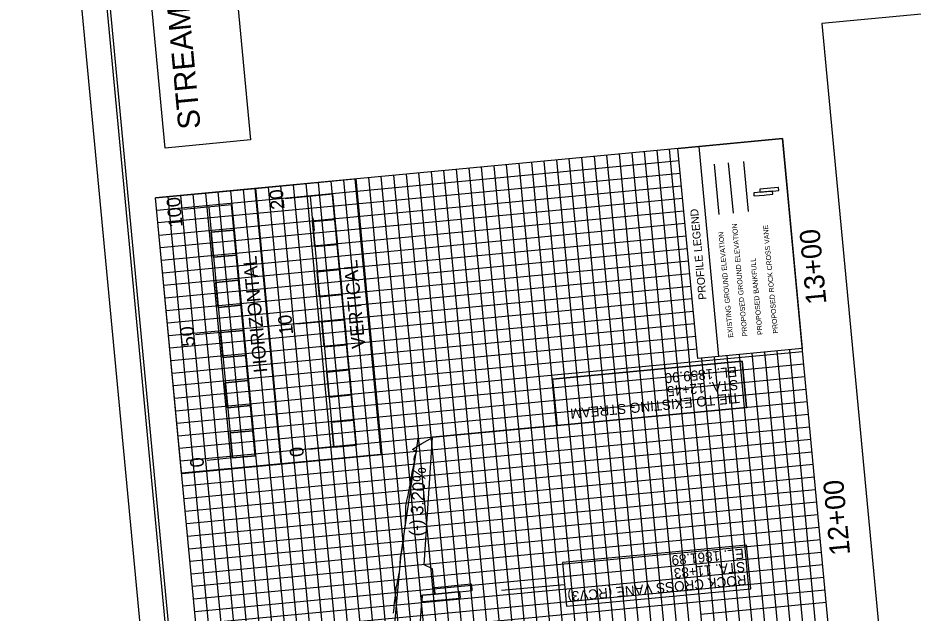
# Model space of a CAD drawing. Extents: x 554635 to 555260, y 497951 to 498841.
# Drawn here: x 554635.2 to 554990.7, y 498281.2 to 498517.4 of the extents above; entities that cross this region are included whole.
import ezdxf

# ---------------------------------------------------------------- set-up
doc = ezdxf.new("R2010")
doc.units = 0
for name, color, linetype in [('Default', 7, 'Continuous'), ('Exist Vertical Profile Ground Line', 7, 'Continuous'), ('Exist Vertical Profile Horizontal Axis Label Major', 7, 'Continuous'), ('Prop Drainage Ditch Boundaries', 7, 'Continuous'), ('Prop Erosion Rip Rap Single Stone CELL', 7, 'Continuous'), ('Prop NEU Vane Rock Cross With Step Pools Detail CELL', 7, 'Continuous'), ('Prop Plan Preparation Fill In Wetlands Legend CELL', 7, 'Continuous'), ('Prop Plan Preparation Sheet Bridge Report Non FEMA CELL', 7, 'Continuous'), ('Prop Vertical Profile Ditch Grade Median', 7, 'Continuous'), ('Prop Vertical Profile Ditch Grade Median Label', 7, 'Continuous'), ('Prop VPI Ditch Grade Median Label', 7, 'Continuous'), ('Prop VPT Ditch Grade Median Label', 7, 'Continuous'), ('Sheet Cross Section Scale CELL', 7, 'Continuous'), ('Sheet Layout Plan Border', 7, 'Continuous'), ('Sheet Plan CELL', 7, 'Continuous'), ('Sheet Plot Border Inside CELL', 7, 'Continuous'), ('Sheet Plot Border Outside CELL', 7, 'Continuous')]:
    doc.layers.add(name, color=color, linetype=linetype)

msp = doc.modelspace()

# ---------------------------------------------------------------- linework, layer by layer
at = {"layer": 'Default'}
msp.add_line((554752.4, 498438.09), (554752.87, 498433.11), dxfattribs=at)
at = {"layer": 'Exist Vertical Profile Ground Line'}
msp.add_line((554913.68, 498439.42), (554911.8, 498459.39), dxfattribs=at)
for points in [[(554787.44, 498304.57), (554787.66, 498305.6), (554787.88, 498306.62), (554788.11, 498307.65), (554788.26, 498308.67), (554788.35, 498309.68), (554788.45, 498310.69), (554788.54, 498311.71), (554788.63, 498312.72), (554788.73, 498313.74), (554788.83, 498314.75), (554788.98, 498315.77), (554789.12, 498316.79), (554789.16, 498317.79), (554789.18, 498318.8), (554789.21, 498319.81), (554789.23, 498320.81), (554789.26, 498321.82), (554789.29, 498322.83), (554789.33, 498323.84), (554789.53, 498324.86), (554789.73, 498325.88), (554789.94, 498326.91), (554790.14, 498327.93), (554790.34, 498328.95), (554790.55, 498329.98), (554790.75, 498331), (554790.94, 498332.02), (554791.12, 498333.05), (554791.3, 498334.07), (554791.48, 498335.09), (554791.67, 498336.11), (554791.85, 498337.13), (554792.03, 498338.15), (554792.26, 498339.18), (554792.51, 498340.21), (554792.67, 498341.23), (554792.63, 498342.23), (554792.73, 498343.24), (554793.16, 498344.29), (554793.6, 498345.33), (554791.9, 498346.18), (554793.62, 498347.34), (554795.68, 498348.54), (554797.75, 498349.74), (554799.81, 498350.94), (554799.85, 498350.97)], [(554784.44, 498281.19), (554784.53, 498282.2), (554784.62, 498283.21), (554784.7, 498284.23), (554784.79, 498285.24), (554784.87, 498286.25), (554784.99, 498287.27), (554785.12, 498288.28), (554785.24, 498289.3), (554785.37, 498290.32), (554785.5, 498291.33), (554785.67, 498292.35), (554785.9, 498293.38), (554786.12, 498294.4), (554786.31, 498295.43), (554786.51, 498296.45), (554786.7, 498297.47), (554786.84, 498298.49), (554786.91, 498299.5), (554786.97, 498300.51), (554787.04, 498301.52), (554787.11, 498302.53), (554787.21, 498303.55), (554787.44, 498304.57)]]:
    msp.add_lwpolyline(points, dxfattribs=at)
at = {"layer": 'Prop Drainage Ditch Boundaries'}
msp.add_line((554925.35, 498440.52), (554923.47, 498460.4), dxfattribs=at)
msp.add_lwpolyline([(554756.46, 498100.75), (554778.24, 498153.03), (554776.77, 498203.12), (554782.76, 498253.91), (554787.47, 498304.58), (554794.13, 498350.41)], dxfattribs=at)
at = {"layer": 'Prop Erosion Rip Rap Single Stone CELL'}
for p, q in [((554927.42, 498447.81), (554927.5, 498446.9)), ((554934.76, 498448.67), (554927.51, 498447.98)), ((554929.79, 498449.29), (554929.87, 498448.37)), ((554937.13, 498450.15), (554929.88, 498449.46)), ((554934.76, 498448.67), (554936.15, 498448.8)), ((554934.97, 498447.6), (554934.88, 498448.51)), ((554936.15, 498448.8), (554937.25, 498448.9)), ((554937.34, 498449.08), (554937.25, 498449.99)), ((554932.39, 498447.19), (554933.78, 498447.32)), ((554933.78, 498447.32), (554934.88, 498447.43)), ((554815.25, 498292.64), (554800.74, 498291.27)), ((554815.67, 498290.5), (554815.49, 498292.33)), ((554795.77, 498288), (554795.65, 498286.15)), ((554800.98, 498288.78), (554796.07, 498288.31)), ((554800.56, 498290.91), (554800.73, 498289.09)), ((554808.74, 498289.51), (554800.98, 498288.78)), ((554810.51, 498289.68), (554808.74, 498289.51)), ((554810.51, 498289.68), (554813.29, 498289.94)), ((554810.92, 498287.54), (554810.75, 498289.37)), ((554813.29, 498289.94), (554815.48, 498290.15)), ((554796.01, 498285.8), (554810.74, 498287.19))]:
    msp.add_line(p, q, dxfattribs=at)
for points in [[(554929.99, 498448.22), (554933.88, 498448.59), (554934.76, 498448.67)], [(554927.62, 498446.74), (554931.51, 498447.11), (554932.39, 498447.19)], [(554800.98, 498288.78), (554808.74, 498289.51), (554810.51, 498289.68)]]:
    msp.add_lwpolyline(points, dxfattribs=at)
for centre, start, end in [((554796.1, 498287.98), 95.4008, 176.3197), ((554795.98, 498286.13), 176.3197, 275.4008)]:
    msp.add_arc(centre, 0.333, start, end, dxfattribs=at)
for centre, major_axis, start_param, end_param in [((554927.52, 498447.82), (0.016, -0.166), 3.141593, 4.712389), ((554929.89, 498449.3), (0.016, -0.166), 3.141593, 4.712389), ((554929.98, 498448.38), (0.016, -0.166), 4.712389, 6.283185), ((554934.78, 498448.5), (-0.016, 0.166), 4.712389, 6.283185), ((554937.15, 498449.98), (-0.016, 0.166), 4.712389, 6.283185), ((554937.23, 498449.07), (0.016, -0.166), 0, 1.570796), ((554927.61, 498446.91), (0.016, -0.166), 4.712389, 6.283185), ((554934.86, 498447.59), (0.016, -0.166), 0, 1.570796), ((554800.77, 498290.93), (0.031, -0.332), 3.141593, 4.712389), ((554815.28, 498292.31), (-0.031, 0.332), 4.712389, 6.283185), ((554800.94, 498289.11), (0.031, -0.332), 4.712389, 6.283185), ((554810.54, 498289.35), (-0.031, 0.332), 5.974663, 6.283185), ((554810.54, 498289.35), (-0.031, 0.332), 4.712389, 5.974663), ((554815.45, 498290.48), (0.031, -0.332), 0, 1.570796), ((554810.71, 498287.52), (0.031, -0.332), 0, 1.570796)]:
    msp.add_ellipse(centre, major_axis=major_axis, ratio=0.64, start_param=start_param, end_param=end_param, dxfattribs=at)
at = {"layer": 'Prop NEU Vane Rock Cross With Step Pools Detail CELL'}
msp.add_lwpolyline([(554693.71, 498465.77), (554674.74, 498666.49), (554708.62, 498669.7), (554727.59, 498468.97)], close=True, dxfattribs=at)
at = {"layer": 'Prop Plan Preparation Fill In Wetlands Legend CELL'}
msp.add_line((554905.61, 498466.41), (554913.49, 498383.06), dxfattribs=at)
msp.add_lwpolyline([(554905.19, 498382.28), (554897.31, 498465.63), (554938.81, 498469.55), (554946.69, 498386.2)], close=True, dxfattribs=at)
at = {"layer": 'Prop Plan Preparation Sheet Bridge Report Non FEMA CELL'}
for p, q in [((554938.81, 498469.55), (554889.03, 498464.85)), ((554975.22, 498084.39), (554938.81, 498469.55)), ((554889.03, 498464.85), (554689.92, 498446.02)), ((554892.11, 498113.58), (554859.16, 498462.02)), ((554897.09, 498114.05), (554864.14, 498462.49)), ((554902.06, 498114.52), (554869.12, 498462.96)), ((554907.04, 498114.99), (554874.1, 498463.43)), ((554912.02, 498115.46), (554879.08, 498463.9)), ((554917, 498115.93), (554884.05, 498464.38)), ((554925.45, 498079.69), (554889.03, 498464.85)), ((554925.45, 498079.69), (554889.03, 498464.85)), ((554926.95, 498116.87), (554894.01, 498465.32)), ((554889.5, 498459.87), (554690.39, 498441.04)), ((554857.26, 498110.28), (554824.32, 498458.73)), ((554862.24, 498110.75), (554829.3, 498459.2)), ((554867.22, 498111.22), (554834.28, 498459.67)), ((554875.67, 498074.98), (554839.25, 498460.14)), ((554877.17, 498112.16), (554844.23, 498460.61)), ((554882.15, 498112.64), (554849.21, 498461.08)), ((554887.13, 498113.11), (554854.19, 498461.55)), ((554897.78, 498460.65), (554889.5, 498459.87)), ((554889.97, 498454.89), (554690.86, 498436.07)), ((554817.44, 498106.52), (554784.5, 498454.96)), ((554825.89, 498070.27), (554789.48, 498455.43)), ((554827.4, 498107.46), (554794.45, 498455.9)), ((554832.37, 498107.93), (554799.43, 498456.38)), ((554837.35, 498108.4), (554804.41, 498456.85)), ((554842.33, 498108.87), (554809.39, 498457.32)), ((554847.31, 498109.34), (554814.36, 498457.79)), ((554852.29, 498109.81), (554819.34, 498458.26)), ((554898.25, 498455.67), (554889.97, 498454.89)), ((554777.62, 498102.75), (554744.68, 498451.2)), ((554782.6, 498103.22), (554749.65, 498451.67)), ((554787.57, 498103.69), (554754.63, 498452.14)), ((554792.55, 498104.16), (554759.61, 498452.61)), ((554797.53, 498104.63), (554764.59, 498453.08)), ((554802.51, 498105.11), (554769.56, 498453.55)), ((554807.48, 498105.58), (554774.54, 498454.02)), ((554812.46, 498106.05), (554779.52, 498454.49)), ((554890.44, 498449.91), (554691.33, 498431.09)), ((554742.77, 498099.46), (554709.83, 498447.9)), ((554747.75, 498099.93), (554714.81, 498448.37)), ((554752.73, 498100.4), (554719.79, 498448.85)), ((554757.71, 498100.87), (554724.76, 498449.32)), ((554762.68, 498101.34), (554729.74, 498449.79)), ((554767.66, 498101.81), (554734.72, 498450.26)), ((554776.11, 498065.57), (554739.7, 498450.73)), ((554898.72, 498450.7), (554890.44, 498449.91)), ((554726.33, 498060.86), (554689.92, 498446.02)), ((554890.91, 498444.94), (554691.8, 498426.11)), ((554727.84, 498098.05), (554694.9, 498446.49)), ((554732.82, 498098.52), (554699.87, 498446.96)), ((554737.8, 498098.99), (554704.85, 498447.43)), ((554899.19, 498445.72), (554890.91, 498444.94)), ((554899.66, 498440.74), (554891.38, 498439.96)), ((554891.38, 498439.96), (554692.27, 498421.13)), ((554891.86, 498434.98), (554692.74, 498416.15)), ((554900.13, 498435.76), (554891.86, 498434.98)), ((554892.33, 498430), (554693.21, 498411.18)), ((554900.6, 498430.78), (554892.33, 498430)), ((554892.8, 498425.02), (554693.68, 498406.2)), ((554901.07, 498425.81), (554892.8, 498425.02)), ((554893.27, 498420.05), (554694.15, 498401.22)), ((554901.54, 498420.83), (554893.27, 498420.05)), ((554902.01, 498415.85), (554893.74, 498415.07)), ((554893.74, 498415.07), (554694.63, 498396.24)), ((554894.21, 498410.09), (554695.1, 498391.27)), ((554902.48, 498410.87), (554894.21, 498410.09)), ((554894.68, 498405.11), (554695.57, 498386.29)), ((554902.95, 498405.89), (554894.68, 498405.11)), ((554895.15, 498400.13), (554696.04, 498381.31)), ((554903.43, 498400.92), (554895.15, 498400.13)), ((554895.62, 498395.16), (554696.51, 498376.33)), ((554903.9, 498395.94), (554895.62, 498395.16)), ((554904.37, 498390.96), (554896.09, 498390.18)), ((554896.09, 498390.18), (554696.98, 498371.35)), ((554896.56, 498385.2), (554697.45, 498366.38)), ((554904.84, 498385.98), (554896.56, 498385.2)), ((554946.81, 498384.93), (554897.03, 498380.22)), ((554946.86, 498118.75), (554921.8, 498383.85)), ((554951.84, 498119.22), (554926.78, 498384.32)), ((554956.82, 498119.69), (554931.76, 498384.79)), ((554961.8, 498120.16), (554936.73, 498385.26)), ((554966.77, 498120.64), (554941.71, 498385.73)), ((554897.03, 498380.22), (554697.92, 498361.4)), ((554931.93, 498117.34), (554906.87, 498382.44)), ((554936.91, 498117.81), (554911.84, 498382.91)), ((554941.89, 498118.28), (554916.82, 498383.38)), ((554947.28, 498379.95), (554897.5, 498375.25)), ((554897.5, 498375.25), (554698.39, 498356.42)), ((554947.75, 498374.97), (554897.97, 498370.27)), ((554897.97, 498370.27), (554698.86, 498351.44)), ((554948.22, 498370), (554898.44, 498365.29)), ((554898.44, 498365.29), (554699.33, 498346.47)), ((554948.69, 498365.02), (554898.91, 498360.31)), ((554898.91, 498360.31), (554699.8, 498341.49)), ((554949.16, 498360.04), (554899.38, 498355.33)), ((554899.38, 498355.33), (554700.27, 498336.51)), ((554949.63, 498355.06), (554899.86, 498350.36)), ((554899.86, 498350.36), (554700.74, 498331.53)), ((554950.1, 498350.09), (554900.33, 498345.38)), ((554900.33, 498345.38), (554701.21, 498326.55)), ((554950.57, 498345.11), (554900.8, 498340.4)), ((554900.8, 498340.4), (554701.68, 498321.58)), ((554951.05, 498340.13), (554901.27, 498335.42)), ((554901.27, 498335.42), (554702.16, 498316.6)), ((554951.52, 498335.15), (554901.74, 498330.45)), ((554901.74, 498330.45), (554702.63, 498311.62)), ((554951.99, 498330.17), (554902.21, 498325.47)), ((554902.21, 498325.47), (554703.1, 498306.64)), ((554952.46, 498325.2), (554902.68, 498320.49)), ((554902.68, 498320.49), (554703.57, 498301.67)), ((554952.93, 498320.22), (554903.15, 498315.51)), ((554903.15, 498315.51), (554704.04, 498296.69)), ((554953.4, 498315.24), (554903.62, 498310.53)), ((554903.62, 498310.53), (554704.51, 498291.71)), ((554953.87, 498310.26), (554904.09, 498305.56)), ((554904.09, 498305.56), (554704.98, 498286.73)), ((554954.34, 498305.28), (554904.56, 498300.58)), ((554904.56, 498300.58), (554705.45, 498281.75)), ((554954.81, 498300.31), (554905.03, 498295.6)), ((554905.03, 498295.6), (554705.92, 498276.78)), ((554955.28, 498295.33), (554905.5, 498290.62)), ((554905.5, 498290.62), (554706.39, 498271.8)), ((554955.75, 498290.35), (554905.97, 498285.65)), ((554905.97, 498285.65), (554706.86, 498266.82)), ((554956.22, 498285.37), (554906.44, 498280.67))]:
    msp.add_line(p, q, dxfattribs=at)
at = {"layer": 'Prop Vertical Profile Ditch Grade Median'}
msp.add_line((554919.33, 498439.95), (554917.43, 498459.96), dxfattribs=at)
msp.add_lwpolyline([(554783.89, 498103.35), (554787.86, 498164.99), (554792.83, 498165.46), (554791.89, 498175.42), (554788.62, 498177.12), (554791.82, 498226.64), (554796.8, 498227.11), (554795.86, 498237.07), (554792.63, 498238.77), (554795.79, 498288.29), (554800.76, 498288.76), (554799.82, 498298.71), (554796.6, 498300.42), (554799.85, 498350.97)], dxfattribs=at)
at = {"layer": 'Prop VPT Ditch Grade Median Label'}
msp.add_line((554827.27, 498290.26), (554852.27, 498292.62), dxfattribs=at)
for points in [[(554849.31, 498355.64), (554847.57, 498374.04), (554922.83, 498381.15), (554924.57, 498362.76)], [(554849.31, 498355.64), (554833.4, 498354.14), (554799.85, 498350.97), (554799.85, 498350.97)], [(554926.2, 498290.86), (554924.56, 498308.21), (554851.45, 498301.3), (554853.09, 498283.95)]]:
    msp.add_lwpolyline(points, close=True, dxfattribs=at)
for points in [[(554924.57, 498362.76), (554922.83, 498381.15), (554847.57, 498374.04), (554849.31, 498355.64), (554924.57, 498362.76)], [(554926.2, 498290.86), (554924.56, 498308.21), (554851.45, 498301.3), (554853.09, 498283.95), (554926.2, 498290.86)]]:
    msp.add_lwpolyline(points, dxfattribs=at)
at = {"layer": 'Sheet Cross Section Scale CELL'}
for p, q in [((554760.32, 498447.42), (554741.31, 498445.63)), ((554769.74, 498347.87), (554760.32, 498447.42)), ((554720.05, 498443.18), (554701.03, 498441.38)), ((554729.46, 498343.62), (554720.05, 498443.18)), ((554762.21, 498427.51), (554761.27, 498437.47)), ((554720.99, 498433.22), (554711.93, 498432.37)), ((554711.93, 498432.37), (554712.87, 498422.41)), ((554721.93, 498423.27), (554720.99, 498433.22)), ((554712.87, 498422.41), (554721.93, 498423.27)), ((554764.09, 498407.6), (554763.15, 498417.56)), ((554723.81, 498403.36), (554722.87, 498413.31)), ((554765.03, 498397.65), (554746.02, 498395.85)), ((554765.03, 498397.65), (554755.97, 498396.79)), ((554755.97, 498396.79), (554756.91, 498386.83)), ((554765.97, 498387.69), (554765.03, 498397.65)), ((554724.75, 498393.4), (554705.74, 498391.6)), ((554724.75, 498393.4), (554715.69, 498392.54)), ((554715.69, 498392.54), (554716.64, 498382.59)), ((554725.7, 498383.45), (554724.75, 498393.4)), ((554756.91, 498386.83), (554765.97, 498387.69)), ((554716.64, 498382.59), (554725.7, 498383.45)), ((554766.91, 498377.73), (554757.85, 498376.88)), ((554757.85, 498376.88), (554758.79, 498366.92)), ((554767.85, 498367.78), (554766.91, 498377.73)), ((554727.58, 498363.53), (554726.64, 498373.49)), ((554758.79, 498366.92), (554767.85, 498367.78)), ((554768.8, 498357.82), (554759.74, 498356.97)), ((554759.74, 498356.97), (554760.68, 498347.01)), ((554769.74, 498347.87), (554768.8, 498357.82)), ((554728.52, 498353.58), (554719.46, 498352.72)), ((554729.46, 498343.62), (554728.52, 498353.58)), ((554760.68, 498347.01), (554750.72, 498346.07)), ((554760.68, 498347.01), (554769.74, 498347.87)), ((554720.4, 498342.77), (554710.45, 498341.82))]:
    msp.add_line(p, q, dxfattribs=at)
for points in [[(554739.78, 498340.42), (554729.45, 498449.76), (554768.97, 498453.5), (554779.31, 498344.16)], [(554700.26, 498336.69), (554689.92, 498446.02), (554729.45, 498449.76), (554739.78, 498340.42)]]:
    msp.add_lwpolyline(points, close=True, dxfattribs=at)
for points in [[(554751.26, 498446.57), (554760.68, 498347.01), (554769.74, 498347.87)], [(554710.99, 498442.32), (554720.4, 498342.77), (554729.46, 498343.62)], [(554762.21, 498427.51), (554753.15, 498426.66), (554752.21, 498436.61), (554761.27, 498437.47)], [(554761.27, 498437.47), (554752.21, 498436.61), (554753.15, 498426.66), (554762.21, 498427.51)], [(554721.93, 498423.27), (554712.87, 498422.41), (554711.93, 498432.37), (554720.99, 498433.22)], [(554764.09, 498407.6), (554755.03, 498406.74), (554754.09, 498416.7), (554763.15, 498417.56)], [(554763.15, 498417.56), (554754.09, 498416.7), (554755.03, 498406.74), (554764.09, 498407.6)], [(554723.81, 498403.36), (554714.75, 498402.5), (554713.81, 498412.46), (554722.87, 498413.31)], [(554722.87, 498413.31), (554713.81, 498412.46), (554714.75, 498402.5), (554723.81, 498403.36)], [(554765.97, 498387.69), (554756.91, 498386.83), (554755.97, 498396.79), (554765.03, 498397.65)], [(554725.7, 498383.45), (554716.64, 498382.59), (554715.69, 498392.54), (554724.75, 498393.4)], [(554767.85, 498367.78), (554758.79, 498366.92), (554757.85, 498376.88), (554766.91, 498377.73)], [(554727.58, 498363.53), (554718.52, 498362.68), (554717.58, 498372.63), (554726.64, 498373.49)], [(554726.64, 498373.49), (554717.58, 498372.63), (554718.52, 498362.68), (554727.58, 498363.53)], [(554769.74, 498347.87), (554760.68, 498347.01), (554759.74, 498356.97), (554768.8, 498357.82)], [(554729.46, 498343.62), (554720.4, 498342.77), (554719.46, 498352.72), (554728.52, 498353.58)], [(554719.46, 498352.72), (554720.4, 498342.77), (554729.46, 498343.62)]]:
    msp.add_lwpolyline(points, dxfattribs=at)
at = {"layer": 'Sheet Layout Plan Border'}
msp.add_lwpolyline([(555232.94, 498108.76), (555192.39, 498537.63), (554954.42, 498515.13), (554994.97, 498086.26)], close=True, dxfattribs=at)
msp.add_lwpolyline([(555232.94, 498108.76), (555192.39, 498537.63), (554954.42, 498515.13), (554994.97, 498086.26)], close=True, dxfattribs=at)
at = {"layer": 'Sheet Plan CELL'}
msp.add_lwpolyline([(554647.23, 498781.63), (554717.82, 498034.95), (555240.49, 498084.36), (555169.9, 498831.04)], close=True, dxfattribs=at)
at = {"layer": 'Sheet Plot Border Inside CELL'}
msp.add_lwpolyline([(555248.96, 498008.08), (555170.55, 498837.37), (554645.4, 498787.73), (554723.81, 497958.43)], close=True, dxfattribs=at)
at = {"layer": 'Sheet Plot Border Outside CELL'}
msp.add_lwpolyline([(555259.53, 498002.55), (555180.3, 498840.56), (554635.23, 498789.03), (554714.46, 497951.01)], close=True, dxfattribs=at)

# ---------------------------------------------------------------- texts
at = {"layer": 'Exist Vertical Profile Horizontal Axis Label Major'}
for s, p in [('13+00', (554956.31, 498404.05)), ('12+00', (554965.72, 498304.5))]:
    msp.add_text(s, height=8, rotation=95.4008, dxfattribs=at).set_placement(p)
at = {"layer": 'Prop NEU Vane Rock Cross With Step Pools Detail CELL'}
msp.add_text('STREAM RELOCATION DETAIL', height=8.7608, rotation=95.4008, dxfattribs=at).set_placement((554707.79, 498473.67))
at = {"layer": 'Prop Plan Preparation Fill In Wetlands Legend CELL'}
for s, height, p in [('PROFILE LEGEND', 3.125, (554908.68, 498405.72)), ('PROPOSED GROUND ELEVATION', 2, (554924.95, 498391.13)), ('PROPOSED ROCK CROSS VANE', 2, (554937.11, 498392.24)), ('EXISTING GROUND ELEVATION', 2, (554919.3, 498390.6)), ('PROPOSED BANKFULL', 2, (554930.97, 498391.7))]:
    msp.add_text(s, height=height, rotation=95.4008, dxfattribs=at).set_placement(p)
at = {"layer": 'Prop Vertical Profile Ditch Grade Median Label'}
msp.add_text('(-) 3.20%', height=5, rotation=86.2991, dxfattribs=at).set_placement((554795.57, 498311.57))
at = {"layer": 'Prop VPI Ditch Grade Median Label'}
for s, p in [('EL. 1859.90', (554920.58, 498379.06)), ('STA. 12+45 ', (554921.08, 498373.84)), ('TIE TO EXISTING STREAM', (554921.57, 498368.62)), ('EL. 1861.89', (554923.33, 498306.83)), ('STA. 11+83 ', (554923.82, 498301.61)), ('ROCK CROSS VANE (RCV3)', (554924.32, 498296.39))]:
    msp.add_text(s, height=4, rotation=185.4008, dxfattribs=at).set_placement(p)
at = {"layer": 'Sheet Cross Section Scale CELL'}
for s, p in [('20', (554741.14, 498441.61)), ('100', (554700.65, 498434.54)), ('HORIZONTAL', (554734.3, 498376.9)), ('VERTICAL', (554773.24, 498386.45)), ('10', (554744.55, 498391.85)), ('50', (554705.6, 498387.26)), ('0', (554748.83, 498343.43)), ('0', (554709.22, 498339.26))]:
    msp.add_text(s, height=5.4, rotation=95.4008, dxfattribs=at).set_placement(p)

doc.saveas('drawing.dxf')
